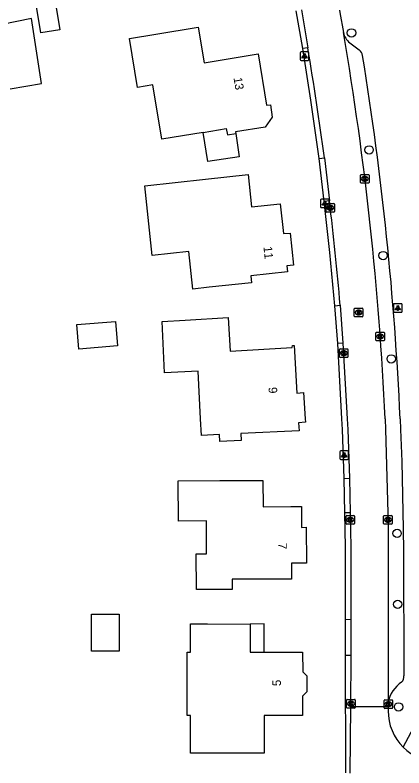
# Model space of a CAD drawing. Extents: x 160457 to 162082, y 388340 to 389736.
# Drawn here: x 160843 to 160888.4, y 388459.2 to 388547.2 of the extents above; entities that cross this region are included whole.
import ezdxf

# ---------------------------------------------------------------- set-up
doc = ezdxf.new("R2010")
doc.units = 0
for name, color, linetype in [('IMGEO_Boom', 7, 'Continuous'), ('IMGEO_Kolk', 7, 'Continuous'), ('IMGEO_Lichtpunt', 7, 'Continuous'), ('IMGEO_Pand', 7, 'Continuous'), ('IMGEO_Pand_nummerreeks', 7, 'Continuous'), ('IMGEO_Pand_overbouw', 7, 'Continuous'), ('IMGEO_Rijbaan_lokaal_open', 7, 'Continuous'), ('IMGEO_Rioolput', 7, 'Continuous'), ('IMGEO_Voetpad_open', 7, 'Continuous')]:
    doc.layers.add(name, color=color, linetype=linetype)

msp = doc.modelspace()

# ---------------------------------------------------------------- linework, layer by layer
at = {"layer": 'IMGEO_Boom'}
for centre in [(160882.237, 388545.072), (160884.288, 388531.4), (160885.923, 388519.055), (160886.869, 388506.981), (160887.56, 388486.61), (160887.621, 388478.317), (160887.729, 388466.33)]:
    msp.add_circle(centre, 0.489, dxfattribs=at)
at = {"layer": 'IMGEO_Kolk'}
for p, q in [((160883.282, 388527.597), (160883.282, 388528.449)), ((160883.357, 388528.523), (160884.209, 388528.523)), ((160883.77, 388528.303), (160883.795, 388528.303)), ((160884.283, 388528.449), (160884.283, 388527.597)), ((160884.209, 388527.523), (160883.357, 388527.523)), ((160883.793, 388527.743), (160883.768, 388527.743)), ((160879.261, 388524.215), (160879.261, 388525.067)), ((160879.336, 388525.141), (160880.188, 388525.141)), ((160879.749, 388524.921), (160879.774, 388524.921)), ((160880.262, 388525.067), (160880.262, 388524.215)), ((160880.188, 388524.141), (160879.336, 388524.141)), ((160879.772, 388524.361), (160879.747, 388524.361)), ((160885.085, 388509.173), (160885.085, 388510.025)), ((160885.16, 388510.099), (160886.012, 388510.099)), ((160885.573, 388509.879), (160885.598, 388509.879)), ((160886.086, 388510.025), (160886.086, 388509.173)), ((160886.012, 388509.099), (160885.16, 388509.099)), ((160885.596, 388509.319), (160885.571, 388509.319)), ((160880.822, 388507.236), (160880.822, 388508.088)), ((160880.897, 388508.162), (160881.749, 388508.162)), ((160881.823, 388508.088), (160881.823, 388507.236)), ((160881.333, 388507.382), (160881.308, 388507.382)), ((160881.31, 388507.942), (160881.335, 388507.942)), ((160881.749, 388507.162), (160880.897, 388507.162)), ((160881.597, 388487.761), (160881.597, 388488.613)), ((160881.672, 388488.687), (160882.524, 388488.687)), ((160882.108, 388487.907), (160882.083, 388487.907)), ((160882.085, 388488.467), (160882.11, 388488.467)), ((160882.598, 388488.613), (160882.598, 388487.761)), ((160885.985, 388487.767), (160885.985, 388488.619)), ((160886.06, 388488.693), (160886.912, 388488.693)), ((160886.496, 388487.913), (160886.471, 388487.913)), ((160886.473, 388488.473), (160886.498, 388488.473)), ((160886.986, 388488.619), (160886.986, 388487.767)), ((160882.524, 388487.687), (160881.672, 388487.687)), ((160886.912, 388487.693), (160886.06, 388487.693)), ((160881.664, 388466.28), (160881.664, 388467.132)), ((160881.739, 388467.206), (160882.591, 388467.206)), ((160882.152, 388466.986), (160882.177, 388466.986)), ((160882.665, 388467.132), (160882.665, 388466.28)), ((160886.036, 388466.223), (160886.036, 388467.075)), ((160886.111, 388467.149), (160886.963, 388467.149)), ((160886.524, 388466.929), (160886.549, 388466.929)), ((160887.037, 388467.075), (160887.037, 388466.223)), ((160882.591, 388466.206), (160881.739, 388466.206)), ((160882.175, 388466.426), (160882.15, 388466.426)), ((160886.963, 388466.149), (160886.111, 388466.149)), ((160886.547, 388466.369), (160886.522, 388466.369))]:
    msp.add_line(p, q, dxfattribs=at)
for points in [[(160883.282, 388527.597), (160883.282, 388528.449)], [(160883.357, 388528.523), (160884.209, 388528.523)], [(160884.283, 388528.449), (160884.283, 388527.597)], [(160884.209, 388527.523), (160883.357, 388527.523)], [(160883.603, 388528.223), (160883.726, 388528.223), (160883.726, 388528.072), (160883.856, 388528.223), (160884.02, 388528.223), (160883.874, 388528.072), (160884.027, 388527.823), (160883.875, 388527.823), (160883.79, 388527.987), (160883.726, 388527.92), (160883.726, 388527.823), (160883.603, 388527.823), (160883.603, 388528.223)], [(160879.261, 388524.215), (160879.261, 388525.067)], [(160879.336, 388525.141), (160880.188, 388525.141)], [(160879.582, 388524.841), (160879.705, 388524.841), (160879.705, 388524.69), (160879.835, 388524.841), (160879.999, 388524.841), (160879.853, 388524.69), (160880.006, 388524.441), (160879.854, 388524.441), (160879.769, 388524.605), (160879.705, 388524.538), (160879.705, 388524.441), (160879.582, 388524.441), (160879.582, 388524.841)], [(160880.262, 388525.067), (160880.262, 388524.215)], [(160880.188, 388524.141), (160879.336, 388524.141)], [(160885.085, 388509.173), (160885.085, 388510.025)], [(160885.16, 388510.099), (160886.012, 388510.099)], [(160886.086, 388510.025), (160886.086, 388509.173)], [(160886.012, 388509.099), (160885.16, 388509.099)], [(160885.406, 388509.799), (160885.529, 388509.799), (160885.529, 388509.648), (160885.659, 388509.799), (160885.823, 388509.799), (160885.677, 388509.648), (160885.83, 388509.399), (160885.678, 388509.399), (160885.593, 388509.563), (160885.529, 388509.496), (160885.529, 388509.399), (160885.406, 388509.399), (160885.406, 388509.799)], [(160880.822, 388507.236), (160880.822, 388508.088)], [(160880.897, 388508.162), (160881.749, 388508.162)], [(160881.823, 388508.088), (160881.823, 388507.236)], [(160881.143, 388507.862), (160881.266, 388507.862), (160881.266, 388507.711), (160881.396, 388507.862), (160881.56, 388507.862), (160881.414, 388507.711), (160881.567, 388507.462), (160881.415, 388507.462), (160881.33, 388507.626), (160881.266, 388507.559), (160881.266, 388507.462), (160881.143, 388507.462), (160881.143, 388507.862)], [(160881.749, 388507.162), (160880.897, 388507.162)], [(160881.597, 388487.761), (160881.597, 388488.613)], [(160881.672, 388488.687), (160882.524, 388488.687)], [(160881.918, 388488.387), (160882.041, 388488.387), (160882.041, 388488.236), (160882.171, 388488.387), (160882.335, 388488.387), (160882.189, 388488.236), (160882.342, 388487.987), (160882.19, 388487.987), (160882.105, 388488.151), (160882.041, 388488.084), (160882.041, 388487.987), (160881.918, 388487.987), (160881.918, 388488.387)], [(160882.598, 388488.613), (160882.598, 388487.761)], [(160885.985, 388487.767), (160885.985, 388488.619)], [(160886.06, 388488.693), (160886.912, 388488.693)], [(160886.306, 388488.393), (160886.429, 388488.393), (160886.429, 388488.242), (160886.559, 388488.393), (160886.723, 388488.393), (160886.577, 388488.242), (160886.73, 388487.993), (160886.578, 388487.993), (160886.493, 388488.157), (160886.429, 388488.09), (160886.429, 388487.993), (160886.306, 388487.993), (160886.306, 388488.393)], [(160886.986, 388488.619), (160886.986, 388487.767)], [(160882.524, 388487.687), (160881.672, 388487.687)], [(160886.912, 388487.693), (160886.06, 388487.693)], [(160881.664, 388466.28), (160881.664, 388467.132)], [(160881.739, 388467.206), (160882.591, 388467.206)], [(160881.985, 388466.906), (160882.108, 388466.906), (160882.108, 388466.755), (160882.238, 388466.906), (160882.402, 388466.906), (160882.256, 388466.755), (160882.409, 388466.506), (160882.257, 388466.506), (160882.172, 388466.67), (160882.108, 388466.603), (160882.108, 388466.506), (160881.985, 388466.506), (160881.985, 388466.906)], [(160882.665, 388467.132), (160882.665, 388466.28)], [(160886.036, 388466.223), (160886.036, 388467.075)], [(160886.111, 388467.149), (160886.963, 388467.149)], [(160886.357, 388466.849), (160886.48, 388466.849), (160886.48, 388466.698), (160886.61, 388466.849), (160886.774, 388466.849), (160886.628, 388466.698), (160886.781, 388466.449), (160886.629, 388466.449), (160886.544, 388466.613), (160886.48, 388466.546), (160886.48, 388466.449), (160886.357, 388466.449), (160886.357, 388466.849)], [(160887.037, 388467.075), (160887.037, 388466.223)], [(160882.591, 388466.206), (160881.739, 388466.206)], [(160886.963, 388466.149), (160886.111, 388466.149)]]:
    msp.add_lwpolyline(points, dxfattribs=at)
for centre, start, end in [((160883.359, 388528.447), 91.55205, 178.44795), ((160883.359, 388528.447), 91.55205, 178.44795), ((160884.207, 388528.447), 1.55205, 88.44795), ((160884.207, 388528.447), 1.55205, 88.44795), ((160883.359, 388527.599), 181.55205, 268.44795), ((160883.359, 388527.599), 181.55205, 268.44795), ((160884.207, 388527.599), 271.55205, 358.44795), ((160884.207, 388527.599), 271.55205, 358.44795), ((160879.338, 388525.065), 91.55205, 178.44795), ((160879.338, 388525.065), 91.55205, 178.44795), ((160880.186, 388525.065), 1.55205, 88.44795), ((160880.186, 388525.065), 1.55205, 88.44795), ((160879.338, 388524.217), 181.55205, 268.44795), ((160879.338, 388524.217), 181.55205, 268.44795), ((160880.186, 388524.217), 271.55205, 358.44795), ((160880.186, 388524.217), 271.55205, 358.44795), ((160885.162, 388510.023), 91.55205, 178.44795), ((160885.162, 388510.023), 91.55205, 178.44795), ((160886.01, 388510.023), 1.55205, 88.44795), ((160886.01, 388510.023), 1.55205, 88.44795), ((160885.162, 388509.175), 181.55205, 268.44795), ((160885.162, 388509.175), 181.55205, 268.44795), ((160886.01, 388509.175), 271.55205, 358.44795), ((160886.01, 388509.175), 271.55205, 358.44795), ((160880.899, 388508.086), 91.55205, 178.44795), ((160880.899, 388508.086), 91.55205, 178.44795), ((160881.747, 388508.086), 1.55205, 88.44795), ((160881.747, 388508.086), 1.55205, 88.44795), ((160880.899, 388507.238), 181.55205, 268.44795), ((160880.899, 388507.238), 181.55205, 268.44795), ((160881.747, 388507.238), 271.55205, 358.44795), ((160881.747, 388507.238), 271.55205, 358.44795), ((160881.674, 388488.611), 91.55205, 178.44795), ((160881.674, 388488.611), 91.55205, 178.44795), ((160882.522, 388488.611), 1.55205, 88.44795), ((160882.522, 388488.611), 1.55205, 88.44795), ((160886.062, 388488.617), 91.55205, 178.44795), ((160886.062, 388488.617), 91.55205, 178.44795), ((160886.91, 388488.617), 1.55205, 88.44795), ((160886.91, 388488.617), 1.55205, 88.44795), ((160881.674, 388487.763), 181.55205, 268.44795), ((160881.674, 388487.763), 181.55205, 268.44795), ((160882.522, 388487.763), 271.55205, 358.44795), ((160882.522, 388487.763), 271.55205, 358.44795), ((160886.062, 388487.769), 181.55205, 268.44795), ((160886.062, 388487.769), 181.55205, 268.44795), ((160886.91, 388487.769), 271.55205, 358.44795), ((160886.91, 388487.769), 271.55205, 358.44795), ((160881.741, 388467.13), 91.55205, 178.44795), ((160881.741, 388467.13), 91.55205, 178.44795), ((160882.589, 388467.13), 1.55205, 88.44795), ((160882.589, 388467.13), 1.55205, 88.44795), ((160886.113, 388467.073), 91.55205, 178.44795), ((160886.113, 388467.073), 91.55205, 178.44795), ((160886.961, 388467.073), 1.55205, 88.44795), ((160886.961, 388467.073), 1.55205, 88.44795), ((160881.741, 388466.282), 181.55205, 268.44795), ((160881.741, 388466.282), 181.55205, 268.44795), ((160882.589, 388466.282), 271.55205, 358.44795), ((160882.589, 388466.282), 271.55205, 358.44795), ((160886.113, 388466.225), 181.55205, 268.44795), ((160886.113, 388466.225), 181.55205, 268.44795), ((160886.961, 388466.225), 271.55205, 358.44795), ((160886.961, 388466.225), 271.55205, 358.44795)]:
    msp.add_arc(centre, 0.0765, start, end, dxfattribs=at)
for centre, major_axis, ratio, start_param, end_param in [((160883.769, 388528.023), (-0.387, 0.002), 0.722429, 4.712389, 7.853982), ((160883.794, 388528.023), (-0.39, 0.002), 0.717154, 1.570796, 4.712389), ((160879.748, 388524.641), (-0.387, 0.002), 0.722429, 4.712389, 7.853982), ((160879.773, 388524.641), (-0.39, 0.002), 0.717154, 1.570796, 4.712389), ((160885.572, 388509.599), (-0.387, 0.002), 0.722429, 4.712389, 7.853982), ((160885.597, 388509.599), (-0.39, 0.002), 0.717154, 1.570796, 4.712389), ((160881.309, 388507.662), (-0.387, 0.002), 0.722429, 4.712389, 7.853982), ((160881.334, 388507.662), (-0.39, 0.002), 0.717154, 1.570796, 4.712389), ((160882.084, 388488.187), (-0.387, 0.002), 0.722429, 4.712389, 7.853982), ((160882.109, 388488.187), (-0.39, 0.002), 0.717154, 1.570796, 4.712389), ((160886.472, 388488.193), (-0.387, 0.002), 0.722429, 4.712389, 7.853982), ((160886.497, 388488.193), (-0.39, 0.002), 0.717154, 1.570796, 4.712389), ((160882.151, 388466.706), (-0.387, 0.002), 0.722429, 4.712389, 7.853982), ((160882.176, 388466.706), (-0.39, 0.002), 0.717154, 1.570796, 4.712389), ((160886.523, 388466.649), (-0.387, 0.002), 0.722429, 4.712389, 7.853982), ((160886.548, 388466.649), (-0.39, 0.002), 0.717154, 1.570796, 4.712389)]:
    msp.add_ellipse(centre, major_axis=major_axis, ratio=ratio, start_param=start_param, end_param=end_param, dxfattribs=at)
at = {"layer": 'IMGEO_Lichtpunt'}
for p, q in [((160876.256, 388542.761), (160876.256, 388541.954)), ((160876.256, 388542.761), (160876.256, 388541.954)), ((160877.158, 388542.856), (160876.35, 388542.856)), ((160877.158, 388542.856), (160876.35, 388542.856)), ((160877.252, 388541.954), (160877.252, 388542.761)), ((160877.252, 388541.954), (160877.252, 388542.761)), ((160876.35, 388541.86), (160877.158, 388541.86)), ((160876.35, 388541.86), (160877.158, 388541.86)), ((160879.536, 388525.655), (160878.728, 388525.655)), ((160879.536, 388525.655), (160878.728, 388525.655)), ((160878.634, 388525.56), (160878.634, 388524.753)), ((160878.634, 388525.56), (160878.634, 388524.753)), ((160879.63, 388524.753), (160879.63, 388525.56)), ((160879.63, 388524.753), (160879.63, 388525.56)), ((160878.728, 388524.659), (160879.536, 388524.659)), ((160878.728, 388524.659), (160879.536, 388524.659)), ((160888.049, 388513.43), (160887.241, 388513.43)), ((160888.049, 388513.43), (160887.241, 388513.43)), ((160887.147, 388513.335), (160887.147, 388512.528)), ((160887.147, 388513.335), (160887.147, 388512.528)), ((160888.143, 388512.528), (160888.143, 388513.335)), ((160888.143, 388512.528), (160888.143, 388513.335)), ((160887.241, 388512.434), (160888.049, 388512.434)), ((160887.241, 388512.434), (160888.049, 388512.434)), ((160880.878, 388496.148), (160880.878, 388495.341)), ((160880.878, 388496.148), (160880.878, 388495.341)), ((160881.78, 388496.243), (160880.972, 388496.243)), ((160881.78, 388496.243), (160880.972, 388496.243)), ((160881.874, 388495.341), (160881.874, 388496.148)), ((160881.874, 388495.341), (160881.874, 388496.148)), ((160880.972, 388495.247), (160881.78, 388495.247)), ((160880.972, 388495.247), (160881.78, 388495.247))]:
    msp.add_line(p, q, dxfattribs=at)
for points in [[(160876.63, 388542.425), (160876.669, 388542.397), (160876.481, 388542.135), (160876.443, 388542.162), (160876.63, 388542.425)], [(160876.732, 388542.377), (160876.779, 388542.377), (160876.779, 388542.055), (160876.732, 388542.055), (160876.732, 388542.377)], [(160876.842, 388542.397), (160876.88, 388542.424), (160877.067, 388542.162), (160877.028, 388542.134), (160876.842, 388542.397)], [(160879.008, 388525.224), (160879.047, 388525.196), (160878.859, 388524.934), (160878.821, 388524.961), (160879.008, 388525.224)], [(160879.11, 388525.176), (160879.157, 388525.176), (160879.157, 388524.854), (160879.11, 388524.854), (160879.11, 388525.176)], [(160879.22, 388525.196), (160879.258, 388525.223), (160879.445, 388524.961), (160879.406, 388524.933), (160879.22, 388525.196)], [(160887.521, 388512.999), (160887.56, 388512.971), (160887.372, 388512.709), (160887.334, 388512.736), (160887.521, 388512.999)], [(160887.623, 388512.951), (160887.67, 388512.951), (160887.67, 388512.629), (160887.623, 388512.629), (160887.623, 388512.951)], [(160887.733, 388512.971), (160887.771, 388512.998), (160887.958, 388512.736), (160887.919, 388512.708), (160887.733, 388512.971)], [(160881.252, 388495.812), (160881.291, 388495.784), (160881.103, 388495.522), (160881.065, 388495.549), (160881.252, 388495.812)], [(160881.354, 388495.764), (160881.401, 388495.764), (160881.401, 388495.442), (160881.354, 388495.442), (160881.354, 388495.764)], [(160881.464, 388495.784), (160881.502, 388495.811), (160881.689, 388495.549), (160881.65, 388495.521), (160881.464, 388495.784)]]:
    msp.add_lwpolyline(points, dxfattribs=at)
for centre in [(160876.755, 388542.559), (160879.133, 388525.358), (160887.646, 388513.133), (160881.377, 388495.946)]:
    msp.add_circle(centre, 0.0994, dxfattribs=at)
for centre, start, end in [((160876.35, 388542.761), 90, 180), ((160876.35, 388542.761), 90, 180), ((160877.158, 388542.761), 0, 90), ((160877.158, 388542.761), 0, 90), ((160876.35, 388541.954), 180, 270), ((160876.35, 388541.954), 180, 270), ((160877.158, 388541.954), 270, 0), ((160877.158, 388541.954), 270, 360), ((160878.728, 388525.56), 90, 180), ((160878.728, 388525.56), 90, 180), ((160879.536, 388525.56), 0, 90), ((160879.536, 388525.56), 0, 90), ((160878.728, 388524.753), 180, 270), ((160878.728, 388524.753), 180, 270), ((160879.536, 388524.753), 270, 0), ((160879.536, 388524.753), 270, 360), ((160887.241, 388513.335), 90, 180), ((160887.241, 388513.335), 90, 180), ((160888.049, 388513.335), 0, 90), ((160888.049, 388513.335), 0, 90), ((160887.241, 388512.528), 180, 270), ((160887.241, 388512.528), 180, 270), ((160888.049, 388512.528), 270, 0), ((160888.049, 388512.528), 270, 360), ((160880.972, 388496.148), 90, 180), ((160880.972, 388496.148), 90, 180), ((160881.78, 388496.148), 0, 90), ((160881.78, 388496.148), 0, 90), ((160880.972, 388495.341), 180, 270), ((160880.972, 388495.341), 180, 270), ((160881.78, 388495.341), 270, 0), ((160881.78, 388495.341), 270, 360)]:
    msp.add_arc(centre, 0.0946, start, end, dxfattribs=at)
at = {"layer": 'IMGEO_Pand'}
for points in [[(160845.989, 388545.06), (160845.36, 388548.862), (160847.562, 388549.226), (160848.19, 388545.424), (160845.989, 388545.06)], [(160842.385, 388538.537), (160846.042, 388539.153), (160844.867, 388546.745), (160832.844, 388544.31)], [(160864.917, 388533.454), (160860.1, 388532.666), (160859.053, 388538.99), (160857.267, 388538.694), (160856.32, 388544.416), (160859.398, 388544.925), (160864.33, 388545.741), (160865.019, 388541.576), (160871.331, 388542.614), (160872.297, 388536.616), (160872.771, 388536.675), (160872.983, 388535.21), (160872.166, 388534.062), (160868.692, 388533.51), (160868.733, 388533.309)], [(160864.917, 388533.454), (160867.586, 388533.891), (160867.744, 388533.158), (160868.733, 388533.309)], [(160868.733, 388533.309), (160869.129, 388530.602), (160865.472, 388530.062), (160864.917, 388533.454)], [(160858.097, 388527.208), (160865.187, 388527.975), (160870.157, 388528.513), (160870.579, 388524.74), (160873.893, 388525.114), (160874.285, 388521.618), (160875.079, 388521.691), (160875.481, 388517.945), (160874.688, 388517.854), (160874.771, 388517.156), (160870.492, 388516.688), (160870.581, 388515.884), (160865.61, 388515.354), (160863.721, 388515.152), (160863.249, 388519.523), (160858.978, 388519.062), (160858.097, 388527.208)], [(160867.823, 388511.813), (160868.054, 388507.878), (160875.325, 388508.33), (160875.34, 388508.554), (160875.549, 388508.564), (160875.853, 388503), (160876.65, 388503.048), (160876.824, 388500), (160876.848, 388499.586), (160876.037, 388499.52), (160876.117, 388498.6), (160869.324, 388498.263), (160869.364, 388497.459), (160866.851, 388497.334), (160866.81, 388498.137), (160864.71, 388498.033), (160864.612, 388500), (160864.336, 388505.569), (160860.417, 388505.375), (160860.121, 388511.353), (160862.832, 388511.515), (160867.823, 388511.813)], [(160854.675, 388511.374), (160854.906, 388508.499), (160850.405, 388508.138), (160850.175, 388511.013), (160854.675, 388511.374)], [(160866.869, 388492.768), (160871.868, 388492.797), (160871.916, 388489.704), (160875.166, 388489.744), (160876.41, 388489.76), (160876.411, 388487.289), (160876.949, 388487.327), (160876.97, 388483.136), (160875.222, 388483.119), (160875.246, 388481.261), (160868.315, 388481.243), (160868.32, 388480.051), (160864.134, 388480.032), (160864.11, 388484.225), (160865.318, 388484.233), (160865.296, 388488.056), (160862.023, 388488.037), (160861.995, 388492.739), (160866.869, 388492.768)], [(160855.128, 388477.161), (160855.133, 388472.835), (160851.905, 388472.831), (160851.9, 388477.157), (160855.128, 388477.161)], [(160870.419, 388476.012), (160870.42, 388472.739), (160872.049, 388472.739), (160876.52, 388472.74), (160876.543, 388470.441), (160877.039, 388469.978), (160877.04, 388468.105), (160876.526, 388467.587), (160876.519, 388465.346), (160872.029, 388465.318), (160872.029, 388460.938), (160867.03, 388460.934), (160863.433, 388460.931), (160863.436, 388465.34), (160863.037, 388465.341), (160863.042, 388472.728), (160863.442, 388472.728), (160863.445, 388476.027), (160865.42, 388476.023), (160870.419, 388476.012)]]:
    msp.add_lwpolyline(points, dxfattribs=at)
at = {"layer": 'IMGEO_Pand_overbouw'}
msp.add_lwpolyline([(160872.049, 388472.739), (160872.022, 388476.027), (160870.419, 388476.012), (160870.42, 388472.739)], close=True, dxfattribs=at)
at = {"layer": 'IMGEO_Rijbaan_lokaal_open'}
for points in [[(160876.384, 388547.761), (160877.135, 388543.331)], [(160880.835, 388547.712), (160880.883, 388547.436), (160881.294, 388545.099)], [(160879.067, 388530.495), (160879.648, 388525.46)], [(160880.909, 388513.255), (160881.237, 388508.814)], [(160881.237, 388508.814), (160881.735, 388500), (160881.789, 388498.75), (160881.986, 388493.043)], [(160886.153, 388500), (160886.207, 388498.75), (160886.503, 388487.591), (160886.519, 388466.843)], [(160881.986, 388493.043), (160882.08, 388489.012)], [(160882.08, 388489.012), (160882.14, 388484.95), (160882.146, 388476.566)], [(160882.146, 388476.566), (160882.143, 388472.345)], [(160882.143, 388472.345), (160882.1, 388466.34)], [(160886.519, 388466.843), (160886.513, 388466.349)], [(160882.1, 388466.34), (160882.045, 388458.6)], [(160886.513, 388466.349), (160882.1, 388466.34)], [(160886.513, 388466.349), (160886.508, 388465.875)]]:
    msp.add_lwpolyline(points, dxfattribs=at)
for centre, radius, start, end in [((160521.135, 388483.484), 365.392, 2.59071, 9.70803), ((160482.256, 388477.333), 400.356, 7.6307, 9.48846), ((160604.258, 388490.84), 277.557, 4.63223, 7.16531), ((160892.491, 388465.863), 5.983, 179.88602, 225.03708), ((160892.491, 388465.861), 5.982, 225.02594, 270.18529)]:
    msp.add_arc(centre, radius, start, end, dxfattribs=at)
at = {"layer": 'IMGEO_Rioolput'}
for p, q in [((160882.564, 388511.976), (160882.564, 388512.828)), ((160882.639, 388512.902), (160883.491, 388512.902)), ((160883.052, 388512.682), (160883.077, 388512.682)), ((160883.565, 388512.828), (160883.565, 388511.976)), ((160883.491, 388511.902), (160882.639, 388511.902)), ((160883.075, 388512.122), (160883.05, 388512.122))]:
    msp.add_line(p, q, dxfattribs=at)
for points in [[(160882.564, 388511.976), (160882.564, 388512.828)], [(160882.639, 388512.902), (160883.491, 388512.902)], [(160883.153, 388512.6), (160882.901, 388512.602), (160882.901, 388512.202)], [(160883.079, 388512.521), (160883.025, 388512.521), (160883.025, 388512.44)], [(160883.565, 388512.828), (160883.565, 388511.976)], [(160883.491, 388511.902), (160882.639, 388511.902)], [(160882.901, 388512.202), (160883.025, 388512.202), (160883.025, 388512.364), (160883.036, 388512.364)], [(160883.025, 388512.44), (160883.077, 388512.44)], [(160883.083, 388512.335), (160883.154, 388512.202), (160883.294, 388512.202), (160883.229, 388512.328)]]:
    msp.add_lwpolyline(points, dxfattribs=at)
for centre, radius, start, end in [((160882.641, 388512.826), 0.0765, 91.55205, 178.44795), ((160882.641, 388512.826), 0.0765, 91.55205, 178.44795), ((160883.085, 388512.425), 0.0964, 77.00612, 93.18647), ((160883.099, 388512.482), 0.0378, 276.66336, 79.67722), ((160883.152, 388512.49), 0.109, 350.36119, 89.41601), ((160883.15, 388512.49), 0.112, 277.58423, 350.98172), ((160883.489, 388512.826), 0.0765, 1.55205, 88.44795), ((160883.489, 388512.826), 0.0765, 1.55205, 88.44795), ((160882.641, 388511.978), 0.0765, 181.55205, 268.44795), ((160882.641, 388511.978), 0.0765, 181.55205, 268.44795), ((160883.035, 388512.311), 0.0533, 26.02933, 88.69889), ((160883.061, 388512.629), 0.19, 274.7715, 282.96867), ((160883.134, 388512.275), 0.108, 29.51342, 73.79051), ((160883.489, 388511.978), 0.0765, 271.55205, 358.44795), ((160883.489, 388511.978), 0.0765, 271.55205, 358.44795)]:
    msp.add_arc(centre, radius, start, end, dxfattribs=at)
for centre, major_axis, ratio, start_param, end_param in [((160883.051, 388512.402), (-0.387, 0.002), 0.722429, 4.712389, 7.853982), ((160883.076, 388512.402), (-0.39, 0.002), 0.717154, 1.570796, 4.712389)]:
    msp.add_ellipse(centre, major_axis=major_axis, ratio=ratio, start_param=start_param, end_param=end_param, dxfattribs=at)
at = {"layer": 'IMGEO_Voetpad_open'}
for points in [[(160876.547, 388543.233), (160875.764, 388547.652)], [(160877.135, 388543.331), (160876.547, 388543.233)], [(160882.024, 388543.926), (160883.124, 388543.08)], [(160878.459, 388530.41), (160877.491, 388537.22), (160876.547, 388543.233)], [(160878.459, 388530.41), (160879.067, 388530.495)], [(160879.043, 388525.38), (160878.459, 388530.41)], [(160879.648, 388525.46), (160879.043, 388525.38)], [(160880.304, 388513.185), (160879.709, 388519.415), (160879.043, 388525.38)], [(160880.304, 388513.185), (160880.909, 388513.255)], [(160880.648, 388508.769), (160880.304, 388513.185)], [(160881.237, 388508.814), (160880.648, 388508.769)], [(160881.37, 388493.004), (160881.166, 388498.75), (160881.113, 388500), (160880.648, 388508.769)], [(160887.915, 388500), (160887.969, 388498.75), (160888.107, 388494.986), (160888.268, 388487.154), (160888.314, 388484.544), (160888.339, 388469.965)], [(160881.37, 388493.004), (160881.986, 388493.043)], [(160881.456, 388489.002), (160881.37, 388493.004)], [(160882.08, 388489.012), (160881.456, 388489.002)], [(160881.544, 388476.563), (160881.528, 388485.011), (160881.456, 388489.002)], [(160881.543, 388472.356), (160881.544, 388476.563)], [(160881.544, 388476.563), (160882.146, 388476.566)], [(160881.556, 388458.643), (160881.543, 388472.356)], [(160882.143, 388472.345), (160881.543, 388472.356)], [(160888.263, 388461.63), (160890.451, 388465.733)]]:
    msp.add_lwpolyline(points, dxfattribs=at)
for centre, radius, start, end in [((160883.294, 388545.53), 2.046, 192.16202, 231.62895), ((160882.491, 388542.233), 1.057, 10.06773, 53.2245), ((160518.811, 388483.296), 369.482, 2.59113, 9.20761), ((160887.424, 388469.871), 0.92, 316.2205, 5.87812), ((160890.181, 388466.151), 3.726, 124.16239, 169.29098)]:
    msp.add_arc(centre, radius, start, end, dxfattribs=at)

# ---------------------------------------------------------------- texts
at = {"layer": 'IMGEO_Pand_nummerreeks'}
for s, rotation, p in [('13', 279.14993, (160868.459, 388539.819)), ('11', 276.12522, (160871.952, 388520.087)), ('9', 273.26263, (160872.543, 388503.67)), ('7', 270.28709, (160873.679, 388485.49)), ('5', 89.99225, (160874, 388468.768))]:
    msp.add_text(s, height=1, rotation=rotation, dxfattribs=at).set_placement(p)

doc.saveas('drawing.dxf')
